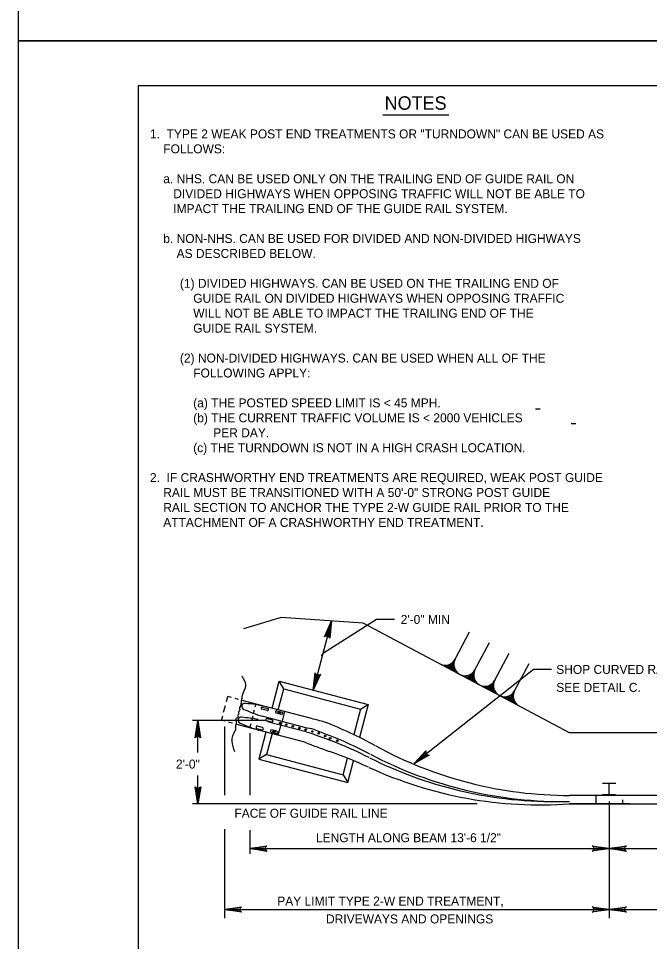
# Model space of a CAD drawing. Extents: x 637628 to 640188, y 298266 to 300751.
# Drawn here: x 638278.5 to 638489.7, y 298558.2 to 298867.1 of the extents above; entities that cross this region are included whole.
import ezdxf

# ---------------------------------------------------------------- set-up
doc = ezdxf.new("R2010")
doc.units = 0
for name, color, linetype in [('1', 7, 'Continuous'), ('2', 7, 'Continuous'), ('3', 7, 'Continuous'), ('PLT-BNDY', 7, 'Continuous')]:
    doc.layers.add(name, color=color, linetype=linetype)

msp = doc.modelspace()

# ---------------------------------------------------------------- linework, layer by layer
at = {"layer": '1'}
msp.add_lwpolyline([(639104.52, 298280.58), (639104.52, 298844.55), (638318.55, 298844.55), (638318.55, 298280.58), (639104.52, 298280.58), (639104.52, 298306.93), (638904.53, 298306.93), (638904.53, 298371.61), (639104.52, 298371.61), (639104.52, 298400.57), (638904.53, 298400.57), (638904.53, 298280.58), (638983.33, 298280.58), (638983.33, 298306.93), (638983.33, 298280.58), (639060.33, 298280.58), (639060.33, 298306.93), (639060.33, 298294.62), (639104.52, 298294.62)], dxfattribs=at)
at = {"layer": '2'}
for p, q in [((638451.52, 298736.47), (638453.09, 298736.47)), ((638463.46, 298731.52), (638465.03, 298731.52)), ((638383.25, 298665.47), (638377.19, 298642.35)), ((638424.66, 298652.65), (638429.51, 298661.77)), ((638431.28, 298649.13), (638436.14, 298658.25)), ((638437.91, 298645.6), (638442.76, 298654.73)), ((638444.53, 298642.08), (638449.38, 298651.21)), ((638367.31, 298642.73), (638365.79, 298645.34)), ((638348.13, 298638.55), (638348.55, 298640.14)), ((638349.77, 298639.82), (638348.55, 298640.14)), ((638352.21, 298639.17), (638351, 298639.49)), ((638347.18, 298634.91), (638347.76, 298637.13)), ((638376.59, 298632.78), (638353.34, 298638.88)), ((638357.78, 298636.68), (638358.04, 298637.65)), ((638360.19, 298636.65), (638361.93, 298636.2)), ((638392.95, 298636), (638395.56, 298637.53)), ((638346.46, 298632.2), (638346.86, 298633.72)), ((638356.2, 298634.94), (638356.2, 298634.94)), ((638356.69, 298632.5), (638357.02, 298633.76)), ((638357.21, 298634.49), (638357.54, 298635.77)), ((638361.71, 298635.47), (638360, 298635.92)), ((638375.13, 298629.63), (638360.05, 298633.58)), ((638360.97, 298636.06), (638360.97, 298636.06)), ((638360.97, 298636.06), (638360.97, 298636.06)), ((638366.51, 298634.21), (638364.8, 298634.66)), ((638364.99, 298635.39), (638366.73, 298634.94)), ((638365.44, 298634.83), (638365.94, 298635.1)), ((638366.11, 298634.88), (638365.44, 298634.83)), ((638365.48, 298634.66), (638365.57, 298635.01)), ((638365.94, 298635.1), (638365.54, 298635.08)), ((638365.57, 298635.01), (638365.6, 298634.54)), ((638365.6, 298634.54), (638365.77, 298635.06)), ((638365.64, 298634.5), (638366.11, 298634.88)), ((638366.06, 298634.68), (638365.64, 298634.5)), ((638365.73, 298634.48), (638365.87, 298635.1)), ((638365.77, 298635.06), (638365.73, 298634.48)), ((638365.76, 298634.8), (638365.76, 298634.8)), ((638365.76, 298634.8), (638365.76, 298634.8)), ((638365.76, 298634.8), (638365.76, 298634.8)), ((638365.87, 298635.1), (638365.9, 298634.51)), ((638365.9, 298634.51), (638366.02, 298635.02)), ((638366.02, 298635.02), (638366.06, 298634.68)), ((638367.54, 298635.15), (638366.49, 298631.18)), ((638367.54, 298635.15), (638367.54, 298635.15)), ((638361.05, 298632.13), (638336.78, 298632.13)), ((638338.58, 298621.45), (638338.58, 298632.13)), ((638347.67, 298631.88), (638346.46, 298632.2)), ((638347.46, 298630.13), (638347.46, 298607.16)), ((638350.15, 298631.23), (638348.76, 298631.59)), ((638374.3, 298624.89), (638351.6, 298630.85)), ((638355.68, 298632.96), (638355.68, 298632.96)), ((638355.95, 298629.71), (638356.34, 298631.17)), ((638360.22, 298629.8), (638358.51, 298630.25)), ((638363.23, 298631.62), (638361.53, 298632.07)), ((638361.53, 298632.07), (638363.26, 298631.61)), ((638361.71, 298632.8), (638363.45, 298632.35)), ((638363.43, 298632.35), (638361.72, 298632.8)), ((638374.77, 298628.31), (638362.24, 298631.59)), ((638362.49, 298632.21), (638362.49, 298632.21)), ((638362.49, 298632.21), (638362.49, 298632.21)), ((638365.45, 298627.21), (638366.49, 298631.18)), ((638355.95, 298627.91), (638355.95, 298607.16)), ((638358.32, 298629.51), (638360.06, 298629.06)), ((638359.29, 298629.65), (638359.29, 298629.65)), ((638359.29, 298629.65), (638359.29, 298629.65)), ((638363.12, 298628.26), (638364.86, 298627.8)), ((638365.02, 298628.54), (638363.31, 298628.99)), ((638363.76, 298628.42), (638364.26, 298628.69)), ((638364.43, 298628.47), (638363.76, 298628.42)), ((638363.8, 298628.25), (638363.89, 298628.6)), ((638364.26, 298628.69), (638363.86, 298628.67)), ((638363.89, 298628.6), (638363.92, 298628.14)), ((638363.92, 298628.14), (638364.09, 298628.66)), ((638363.96, 298628.09), (638364.43, 298628.47)), ((638364.38, 298628.27), (638363.96, 298628.09)), ((638364.05, 298628.07), (638364.19, 298628.7)), ((638364.09, 298628.66), (638364.05, 298628.07)), ((638364.08, 298628.4), (638364.08, 298628.4)), ((638364.08, 298628.39), (638364.08, 298628.39)), ((638364.08, 298628.39), (638364.08, 298628.39)), ((638364.19, 298628.7), (638364.22, 298628.1)), ((638364.22, 298628.1), (638364.34, 298628.61)), ((638364.34, 298628.61), (638364.38, 298628.27)), ((638365.45, 298627.21), (638365.45, 298627.21)), ((638483.15, 298628.08), (638462.97, 298628.08)), ((638634.69, 298628.04), (638462.97, 298628.04)), ((638361.54, 298620.73), (638358.93, 298619.2)), ((638338.58, 298604.23), (638338.58, 298613.73)), ((638387.18, 298614), (638388.7, 298611.39)), ((638474.01, 298611.17), (638478.39, 298611.17)), ((638476.24, 298606.89), (638476.24, 298611.03)), ((638476.24, 298606.89), (638476.24, 298611.03)), ((638483.15, 298607.08), (638462.97, 298607.08)), ((638634.69, 298607.04), (638462.97, 298607.04)), ((638471.83, 298604.34), (638471.83, 298606.93)), ((638473.97, 298607.34), (638478.35, 298607.34)), ((638480.78, 298604.52), (638480.78, 298605.63)), ((638432, 298604.23), (638336.78, 298604.23)), ((638483.15, 298604.23), (638462.97, 298604.23)), ((638634.69, 298604.19), (638462.97, 298604.19)), ((638476.24, 298605.09), (638476.24, 298565.96)), ((638347.46, 298595.79), (638347.46, 298565.96)), ((638355.95, 298595.48), (638355.95, 298587.49)), ((638355.95, 298589.29), (638476.24, 298589.29)), ((638476.24, 298589.29), (638586.15, 298589.29)), ((638347.46, 298568.9), (638476.24, 298568.9)), ((638476.24, 298568.9), (638568.48, 298568.9))]:
    msp.add_line(p, q, dxfattribs=at)
for points in [[(638393.92, 298664.73), (638366.42, 298666.64), (638353.81, 298662.83)], [(638404.36, 298665.92), (638398.36, 298665.92), (638380.3, 298654.44)], [(638381.21, 298660.37), (638381.64, 298660.47), (638383.25, 298665.47), (638381.21, 298660.37), (638380.91, 298660.16), (638383.25, 298665.47), (638382.18, 298660.34), (638382.5, 298660.05), (638383.25, 298665.47), (638382.68, 298659.7), (638382.5, 298660.05)], [(638462.97, 298628.08), (638393.92, 298664.73)], [(638421.5, 298650.44), (638424.51, 298648.8), (638422.25, 298650.43), (638424.13, 298649.57), (638422.79, 298650.57), (638423.96, 298650.31), (638423.5, 298650.85), (638424.01, 298650.78), (638423.82, 298651.27), (638424.05, 298651.58), (638423.92, 298649.61), (638424.55, 298648.75)], [(638456.88, 298649.18), (638450.88, 298649.18), (638410.92, 298617.72)], [(638419.59, 298651.1), (638446.08, 298637.01)], [(638421.37, 298650.38), (638422.6, 298650.47), (638423.96, 298651.43)], [(638379.23, 298647.44), (638378.8, 298647.35), (638377.19, 298642.35), (638379.23, 298647.44), (638379.54, 298647.65), (638377.19, 298642.35), (638378.27, 298647.48), (638377.94, 298647.77), (638377.19, 298642.35), (638377.76, 298648.12), (638377.94, 298647.77)], [(638428.04, 298646.8), (638429.28, 298646.89), (638430.64, 298647.85)], [(638428.22, 298646.89), (638431.23, 298645.26), (638428.98, 298646.89), (638430.85, 298646.02), (638429.51, 298647.03), (638430.69, 298646.77), (638430.22, 298647.31), (638430.74, 298647.23), (638430.54, 298647.73), (638430.77, 298648.04), (638430.64, 298646.07), (638431.27, 298645.21)], [(638363.4, 298636.24), (638365.79, 298645.34), (638395.56, 298637.53), (638392.66, 298626.48)], [(638365.47, 298635.7), (638367.31, 298642.73), (638392.95, 298636), (638390.7, 298627.43)], [(638434.77, 298643.38), (638436, 298643.48), (638437.36, 298644.43)], [(638434.79, 298643.43), (638437.8, 298641.8), (638435.55, 298643.43), (638437.42, 298642.56), (638436.08, 298643.57), (638437.26, 298643.31), (638436.79, 298643.85), (638437.31, 298643.77), (638437.11, 298644.27), (638437.34, 298644.58), (638437.21, 298642.61), (638437.84, 298641.75)], [(638441.3, 298639.85), (638442.53, 298639.94), (638443.89, 298640.9)], [(638441.44, 298639.87), (638444.45, 298638.23), (638442.19, 298639.86), (638444.07, 298639), (638442.73, 298640), (638443.9, 298639.74), (638443.44, 298640.28), (638443.95, 298640.21), (638443.76, 298640.7), (638443.99, 298641.01), (638443.86, 298639.04), (638444.49, 298638.18)], [(638337.89, 298626.68), (638338.29, 298626.89), (638338.58, 298632.13), (638337.89, 298626.68), (638337.65, 298626.4), (638338.58, 298632.13), (638338.84, 298626.89), (638339.23, 298626.7), (638338.58, 298632.13), (638339.49, 298626.4), (638339.23, 298626.7)], [(638361.32, 298628.3), (638358.93, 298619.2), (638388.7, 298611.39), (638390.62, 298618.71)], [(638363.39, 298627.76), (638361.54, 298620.73), (638387.18, 298614), (638388.63, 298619.53)], [(638415.62, 298620.55), (638415.22, 298620.74), (638410.92, 298617.72), (638415.62, 298620.55), (638415.99, 298620.54), (638410.92, 298617.72), (638414.88, 298621.16), (638414.79, 298621.59), (638410.92, 298617.72), (638414.86, 298621.98), (638414.79, 298621.59)], [(638339.26, 298609.68), (638338.87, 298609.48), (638338.58, 298604.23), (638339.26, 298609.68), (638339.5, 298609.96), (638338.58, 298604.23), (638338.32, 298609.48), (638337.93, 298609.67), (638338.58, 298604.23), (638337.67, 298609.96), (638337.93, 298609.67)], [(638361.4, 298588.61), (638361.2, 298589), (638355.95, 298589.29), (638361.4, 298588.61), (638361.68, 298588.37), (638355.95, 298589.29), (638361.2, 298589.55), (638361.39, 298589.94), (638355.95, 298589.29), (638361.68, 298590.2), (638361.39, 298589.94)], [(638470.79, 298589.98), (638470.99, 298589.58), (638476.24, 298589.29), (638470.79, 298589.98), (638470.51, 298590.22), (638476.24, 298589.29), (638471, 298589.03), (638470.81, 298588.64), (638476.24, 298589.29), (638470.51, 298588.38), (638470.81, 298588.64)], [(638481.69, 298588.61), (638481.49, 298589), (638476.24, 298589.29), (638481.69, 298588.61), (638481.97, 298588.37), (638476.24, 298589.29), (638481.48, 298589.55), (638481.67, 298589.94), (638476.24, 298589.29), (638481.97, 298590.2), (638481.67, 298589.94)], [(638352.91, 298568.22), (638352.71, 298568.61), (638347.46, 298568.9), (638352.91, 298568.22), (638353.19, 298567.98), (638347.46, 298568.9), (638352.7, 298569.16), (638352.89, 298569.55), (638347.46, 298568.9), (638353.19, 298569.81), (638352.89, 298569.55)], [(638470.79, 298569.59), (638470.99, 298569.19), (638476.24, 298568.9), (638470.79, 298569.59), (638470.51, 298569.83), (638476.24, 298568.9), (638471, 298568.64), (638470.81, 298568.25), (638476.24, 298568.9), (638470.51, 298567.99), (638470.81, 298568.25)], [(638481.69, 298568.22), (638481.49, 298568.61), (638476.24, 298568.9), (638481.69, 298568.22), (638481.97, 298567.98), (638476.24, 298568.9), (638481.48, 298569.16), (638481.67, 298569.55), (638476.24, 298568.9), (638481.97, 298569.81), (638481.67, 298569.55)]]:
    msp.add_lwpolyline(points, dxfattribs=at)
for centre, radius in [((638365.77, 298634.8), 0.389), ((638366.04, 298631.3), 0.27), ((638368.19, 298630.74), 0.27), ((638370.34, 298630.18), 0.27), ((638364.08, 298628.4), 0.389), ((638372.49, 298629.61), 0.27), ((638374.66, 298629.04), 0.27), ((638376.83, 298628.47), 0.27), ((638379, 298627.9), 0.27), ((638381.15, 298626.98), 0.27), ((638382.82, 298626.17), 0.27), ((638385.21, 298625.36), 0.27)]:
    msp.add_circle(centre, radius, dxfattribs=at)
for centre, radius, start, end in [((638421.35, 298654.41), 3.75, 242.0001, 332.0001), ((638427.97, 298650.89), 3.75, 152.0001, 332.0001), ((638434.6, 298647.37), 3.75, 152.0001, 332.0001), ((638441.22, 298643.84), 3.75, 152.0001, 332.0001), ((638447.84, 298640.32), 3.75, 152.0001, 242.0001), ((638354.24, 298636.87), 1.03, 75.3028, 255.3028), ((638349.29, 298582.07), 56.04, 78.0238, 84.6692), ((638360.1, 298636.29), 0.379, 76.5614, 254.6742), ((638361.81, 298635.84), 0.379, 254.0269, 72.1264), ((638353.02, 298632.24), 1.03, 75.3028, 255.3028), ((638348.08, 298577.43), 56.04, 79.0294, 84.6692), ((638376.83, 298687.06), 56.04, 245.9365, 252.5818), ((638364.9, 298635.03), 0.379, 76.5614, 254.6742), ((638366.61, 298634.58), 0.379, 254.0269, 72.1264), ((638375.61, 298682.42), 56.04, 245.9365, 252.5818), ((638358.42, 298629.88), 0.379, 75.9314, 254.0442), ((638361.62, 298632.44), 0.379, 76.5614, 254.6742), ((638361.62, 298632.44), 0.379, 75.9314, 254.0442), ((638363.33, 298631.99), 0.379, 254.0269, 72.1264), ((638363.33, 298631.99), 0.379, 258.4792, 76.5787), ((637734.54, 296176.33), 2538.97, 75.25171, 75.35206), ((638333.08, 298506.94), 133.56, 60.9127, 69.0233), ((638360.13, 298629.43), 0.379, 258.4792, 76.5787), ((638363.22, 298628.62), 0.379, 75.9314, 254.0442), ((638364.93, 298628.17), 0.379, 258.4792, 76.5787), ((638336.54, 298503.73), 130.29, 62.9127, 72.9394), ((638374, 298619.47), 10.22, 65.7931, 83.6654), ((638334.79, 298505.95), 130.29, 61.9127, 70.54), ((638508.63, 298968.43), 368.86, 248.6428, 250.028), ((638340.18, 298498.12), 130.72, 64.9127, 71.0442), ((638460.55, 298743.55), 138.51, 242.3521, 271), ((638462.97, 298742.32), 135.24, 241.3521, 270), ((638458.13, 298743.5), 138.51, 243.3521, 272), ((638453.34, 298741.98), 138.08, 245.3521, 274)]:
    msp.add_arc(centre, radius, start, end, dxfattribs=at)
msp.add_spline([(638350.96, 298621.67), (638350.05, 298625.24), (638350.99, 298628.67), (638351.2, 298629.02), (638351.27, 298629.29), (638351.25, 298629.88), (638351.3, 298630.5), (638351.49, 298631.26), (638351.51, 298631.78), (638351.49, 298633), (638351.88, 298633.19), (638352.14, 298634.16), (638352.31, 298634.35), (638352.23, 298634.95), (638352.7, 298635.87), (638352.6, 298636.13), (638352.8, 298636.89), (638353.12, 298638.13), (638353.2, 298638.87), (638353.25, 298639.26), (638353.4, 298640.09), (638353.46, 298640.54), (638354.6, 298643.63), (638353.39, 298646.97)], degree=3, dxfattribs=at)
at = {"layer": '3'}
msp.add_line((638400.43, 298834.87), (638422.59, 298834.87), dxfattribs=at)
at = {"layer": 'PLT-BNDY'}
for points in [[(638278.52, 299453.58), (639119.52, 299453.58), (639119.52, 298859.58), (638278.52, 298859.58)], [(638278.52, 298859.58), (639119.52, 298859.58), (639119.52, 298265.58), (638278.52, 298265.58)]]:
    msp.add_lwpolyline(points, close=True, dxfattribs=at)

# ---------------------------------------------------------------- texts
at = {"layer": '1'}
msp.add_text('2\'-0"', height=3, dxfattribs=at).set_placement((638331.22, 298616.07))
at = {"layer": '3'}
for s, height, p in [('NOTES', 4.5, (638401.05, 298836.53)), ('1.  TYPE 2 WEAK POST END TREATMENTS OR "TURNDOWN" CAN BE USED AS', 3, (638322.52, 298826.94)), ('    FOLLOWS:', 3, (638322.52, 298821.94)), ('    a. NHS. CAN BE USED ONLY ON THE TRAILING END OF GUIDE RAIL ON', 3, (638322.52, 298811.94)), ('       DIVIDED HIGHWAYS WHEN OPPOSING TRAFFIC WILL NOT BE ABLE TO', 3, (638322.52, 298806.94)), ('       IMPACT THE TRAILING END OF THE GUIDE RAIL SYSTEM.', 3, (638322.52, 298801.94)), ('    b. NON-NHS. CAN BE USED FOR DIVIDED AND NON-DIVIDED HIGHWAYS', 3, (638322.52, 298791.94)), ('        AS DESCRIBED BELOW.', 3, (638322.52, 298786.94)), ('         (1) DIVIDED HIGHWAYS. CAN BE USED ON THE TRAILING END OF ', 3, (638322.52, 298776.94)), ('             GUIDE RAIL ON DIVIDED HIGHWAYS WHEN OPPOSING TRAFFIC ', 3, (638322.52, 298771.94)), ('             WILL NOT BE ABLE TO IMPACT THE TRAILING END OF THE ', 3, (638322.52, 298766.94)), ('             GUIDE RAIL SYSTEM.', 3, (638322.52, 298761.94)), ('         (2) NON-DIVIDED HIGHWAYS. CAN BE USED WHEN ALL OF THE ', 3, (638322.52, 298751.94)), ('             FOLLOWING APPLY:', 3, (638322.52, 298746.94)), ('             (a) THE POSTED SPEED LIMIT IS < 45 MPH.', 3, (638322.52, 298736.94)), ('             (b) THE CURRENT TRAFFIC VOLUME IS < 2000 VEHICLES ', 3, (638322.52, 298731.94)), ('                   PER DAY.', 3, (638322.52, 298726.94)), ('             (c) THE TURNDOWN IS NOT IN A HIGH CRASH LOCATION. ', 3, (638322.52, 298721.94)), ('2.  IF CRASHWORTHY END TREATMENTS ARE REQUIRED, WEAK POST GUIDE', 3, (638322.52, 298711.94)), ('    RAIL MUST BE TRANSITIONED WITH A 50\'-0" STRONG POST GUIDE ', 3, (638322.52, 298706.94)), ('    RAIL SECTION TO ANCHOR THE TYPE 2-W GUIDE RAIL PRIOR TO THE ', 3, (638322.52, 298701.94)), ('    ATTACHMENT OF A CRASHWORTHY END TREATMENT. ', 3, (638322.52, 298696.94)), ('2\'-0" MIN', 3, (638406.43, 298664.48)), ('SHOP CURVED RAIL,', 2.9999, (638458.47, 298647.74)), ('SEE DETAIL C.', 2.9999, (638458.47, 298641.74)), ('FACE OF GUIDE RAIL LINE', 2.9999, (638350.79, 298599.61)), ('LENGTH ALONG BEAM 13\'-6 1/2"', 2.9999, (638378.06, 298591.44)), ('PAY LIMIT TYPE 2-W END TREATMENT,', 2.9999, (638365.12, 298570.24)), ('DRIVEWAYS AND OPENINGS', 2.9999, (638381.45, 298564.25))]:
    msp.add_text(s, height=height, dxfattribs=at).set_placement(p)
msp.add_text('.', height=3.6, rotation=180, dxfattribs=at).set_placement((638380.65, 298654.33))

doc.saveas('drawing.dxf')
